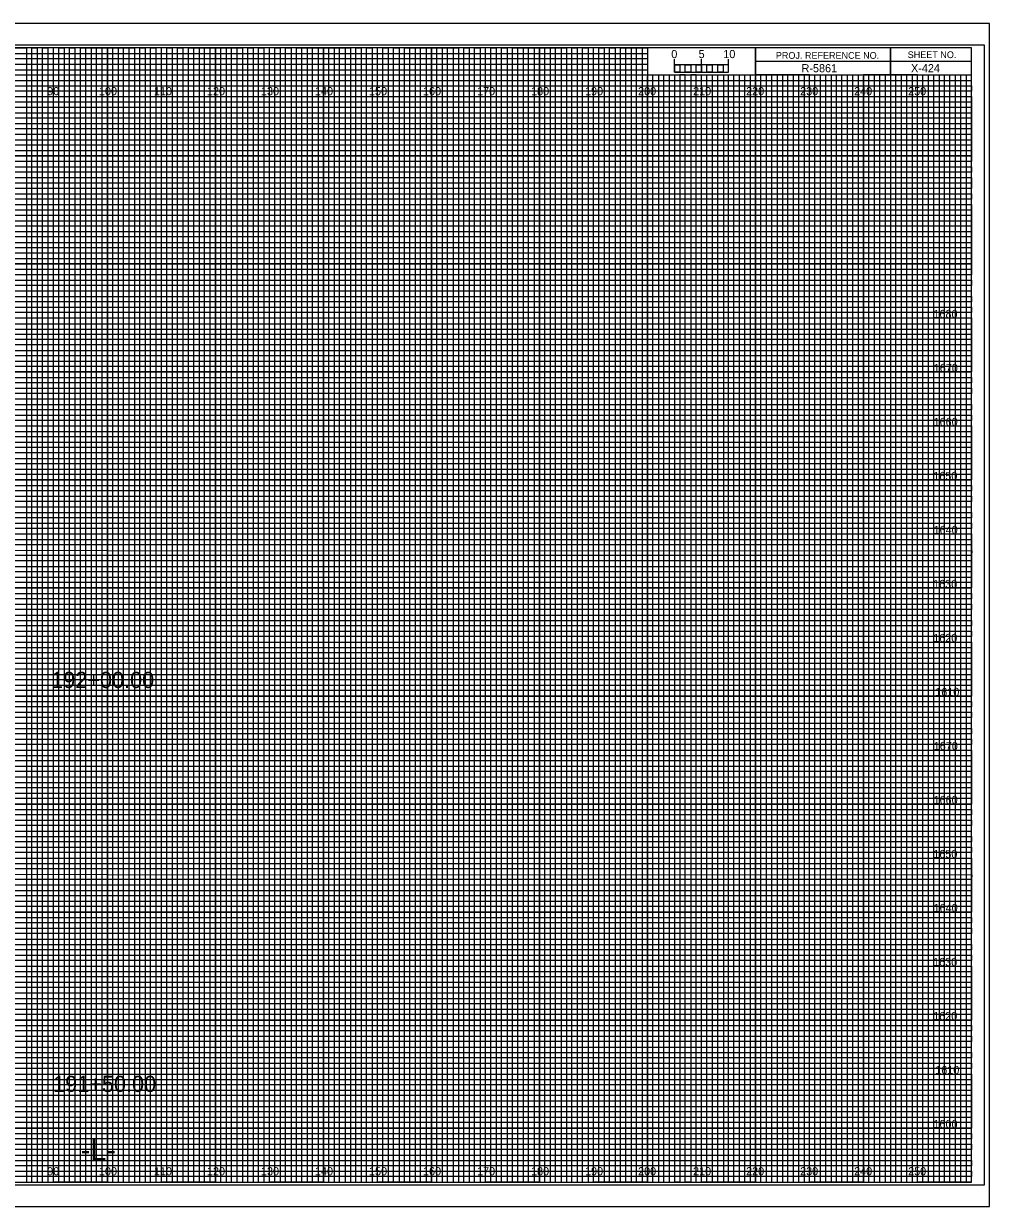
# Model space of a CAD drawing. Extents: x -13 to 323, y -5 to 6154.
# Drawn here: x 144.5 to 323.3, y 4395.5 to 4614.5 of the extents above; entities that cross this region are included whole.
import ezdxf

# ---------------------------------------------------------------- set-up
doc = ezdxf.new("R2010")
doc.units = 0
for name, color, linetype in [('Exist CMT Ground Line', 7, 'Continuous'), ('Prop Horizontal Alignment', 7, 'Continuous'), ('Prop Retaining Wall', 7, 'Continuous'), ('Prop XS Alignment Label', 7, 'Continuous'), ('Prop XS Bar Scale Labels', 7, 'Continuous'), ('Prop XS DDE', 7, 'Continuous'), ('Prop XS DDE Elevations', 7, 'Continuous'), ('Prop XS DDE Slope Text', 7, 'Continuous'), ('Prop XS Earthwork Shape', 7, 'Continuous'), ('Prop XS Elevation Labels', 7, 'Continuous'), ('Prop XS Project Number', 7, 'Continuous'), ('Prop XS Sheet Number', 7, 'Continuous'), ('Prop XS Station Labels', 7, 'Continuous'), ('Raster_Level_0', 7, 'Continuous'), ('Scratch_Level_3', 7, 'Continuous'), ('Sheet Cutting Line CELL', 7, 'Continuous')]:
    doc.layers.add(name, color=color, linetype=linetype)

msp = doc.modelspace()

# ---------------------------------------------------------------- linework, layer by layer
at = {"layer": 'Exist CMT Ground Line'}
for p, q in [((265, 4605.49), (265, 4607.9)), ((265, 4606.9), (265, 4607.9)), ((270, 4605.49), (270, 4607.9)), ((275, 4605.49), (275, 4607.9)), ((275, 4606.9), (275, 4607.9))]:
    msp.add_line(p, q, dxfattribs=at)
for points in [[(275, 4606.9), (265, 4606.9), (265, 4605.49), (275, 4605.49)], [(265, 4606.9), (266, 4606.9), (266, 4605.49), (265, 4605.49)], [(267, 4606.9), (268, 4606.9), (268, 4605.49), (267, 4605.49)], [(269, 4606.9), (270, 4606.9), (270, 4605.49), (269, 4605.49)], [(271, 4606.9), (272, 4606.9), (272, 4605.49), (271, 4605.49)], [(273, 4606.9), (274, 4606.9), (274, 4605.49), (273, 4605.49)]]:
    msp.add_lwpolyline(points, close=True, dxfattribs=at)
at = {"layer": 'Prop Retaining Wall'}
for p, q in [((0, 4609), (260, 4609)), ((260, 4607.98), (0, 4607.98)), ((260, 4609), (260, 4607.98)), ((0, 4607), (260, 4607)), ((260, 4605.89), (0, 4605.89)), ((260, 4607), (260, 4605.89)), ((0, 4604), (320, 4604))]:
    msp.add_line(p, q, dxfattribs=at)
for points in [[(0, 4603), (270, 4603), (320, 4603), (320, 4602), (0, 4602)], [(0, 4601), (320, 4601), (320, 4599), (0, 4599)], [(0, 4598), (320, 4598), (320, 4597), (0, 4596.98)], [(0, 4596), (320, 4596), (320, 4594), (0, 4594)], [(0, 4593), (320, 4593), (320, 4592), (0, 4592)], [(0, 4591), (320, 4591), (320, 4589), (0, 4589)], [(0, 4588), (320, 4588), (320, 4587), (0, 4587)], [(0, 4586), (320, 4586), (320, 4584), (0, 4584)], [(0, 4583), (320, 4583), (320, 4582), (0, 4582)], [(0, 4581), (320, 4581), (320, 4579), (0, 4579)], [(0, 4578), (320, 4578), (320, 4577), (0, 4577)], [(0, 4576), (320, 4576), (320, 4573.95), (320, 4573), (320, 4572), (0, 4572)], [(0, 4574), (320, 4574), (320, 4573), (0, 4573)], [(0, 4571), (320, 4571), (320, 4569), (0, 4569.03)], [(0, 4569.03), (320, 4569), (320, 4568), (0, 4568)], [(0, 4567), (320, 4567), (320, 4566), (0, 4566)], [(0, 4564), (320, 4564), (320, 4563), (0, 4563)], [(0, 4562), (320, 4562), (320, 4561), (0, 4561)], [(-0.07, 4558.89), (320, 4558.89), (320, 4557.88), (-0.07, 4557.88)], [(0, 4557), (320, 4557), (320, 4556), (0, 4556)], [(0, 4554), (320, 4554), (320, 4553), (0, 4553)], [(0, 4552), (320, 4552), (320, 4551), (0, 4551)], [(0, 4549), (320, 4549), (320, 4548), (0, 4548)], [(0, 4547), (320, 4547), (320, 4546), (0, 4546)], [(0, 4544), (320, 4544), (320, 4543), (0, 4543)], [(0, 4542), (320, 4542), (320, 4541), (0, 4541)], [(0, 4539), (320, 4539), (319.99, 4537.98), (0, 4538)], [(0, 4537), (320, 4537), (320, 4536), (0, 4536)], [(0, 4534), (320, 4534), (320, 4533), (0, 4533)], [(0, 4532), (320, 4532), (320, 4531), (0, 4531)], [(0, 4529), (320, 4529), (320, 4528), (0, 4528)], [(0, 4527), (320, 4527), (320, 4526), (0, 4526)], [(0, 4524), (320, 4524), (320, 4523), (0, 4523)], [(0, 4522), (320, 4522), (320, 4521), (0, 4521)], [(0, 4519), (320, 4519), (320, 4518), (0, 4518)], [(0, 4516.99), (320.07, 4516.91), (320, 4516), (0, 4516)], [(0, 4514), (320, 4514), (320, 4513), (0, 4513)], [(0, 4512), (320, 4512), (320, 4511), (0, 4511)], [(0, 4509), (320, 4509), (320, 4508), (0, 4508)], [(0, 4507), (320, 4507), (320, 4506), (0, 4506)], [(0, 4504), (320, 4504), (320, 4503), (0, 4503)], [(0, 4502), (320, 4502), (320, 4501), (0, 4501)], [(0, 4499), (320, 4499), (320, 4498), (0, 4498)], [(0, 4497), (320, 4497), (320, 4496), (0, 4496)], [(0, 4494), (320, 4494), (320, 4493), (0, 4493)], [(0, 4492), (320, 4492), (320, 4491), (0, 4491)], [(0, 4489), (320, 4489), (320, 4488), (0, 4488)], [(0, 4487), (320, 4487), (320, 4486), (0, 4486)], [(0, 4484), (320, 4484), (320, 4483), (0, 4483)], [(0, 4482), (320, 4482), (320, 4481), (0, 4481)], [(0, 4479), (320, 4479), (319.99, 4477.98), (0, 4478)], [(0, 4477), (320, 4477), (320, 4476), (0, 4476)], [(0, 4474), (320, 4474), (320, 4473), (0, 4473)], [(0, 4472), (320, 4472), (320, 4471), (0, 4471)], [(0, 4469), (320, 4469), (320, 4468), (0, 4468)], [(0, 4467), (320, 4467), (320, 4466), (0, 4466)], [(0, 4464), (320, 4464), (320, 4463), (0, 4463)], [(0, 4462), (320, 4462), (320, 4461), (0, 4461)], [(0, 4459), (320, 4459), (320, 4458), (0, 4458)], [(0, 4456.99), (320.07, 4456.91), (320, 4456), (0, 4456)], [(0, 4454), (320, 4454), (320, 4453), (0, 4453)], [(0, 4452), (320, 4452), (320, 4451), (0, 4451)], [(0, 4449), (320, 4449), (320, 4448), (0, 4448)], [(0, 4447), (320, 4447), (320, 4446), (0, 4446)], [(0, 4444), (320, 4444), (320, 4443), (0, 4443)], [(0, 4442), (320, 4442), (320, 4441), (0, 4441)], [(0, 4439), (320, 4439), (320, 4438), (0, 4438)], [(0, 4437), (320, 4437), (320, 4436), (0, 4436)], [(0, 4434), (320, 4434), (320, 4433), (0, 4433)], [(0, 4432), (320, 4432), (320, 4431), (0, 4431)], [(0, 4429), (320, 4429), (320, 4428), (0, 4428)], [(0, 4427), (320, 4427), (320, 4426), (0, 4426)], [(0, 4424), (320, 4424), (320, 4423), (0, 4423)], [(0, 4422), (320, 4422), (320, 4421), (0, 4421)], [(0, 4419), (320, 4419), (320, 4418), (0, 4418)], [(0, 4417), (320, 4417), (320, 4416), (0, 4416)], [(0, 4414), (320, 4414), (320, 4413), (0, 4413)], [(0, 4412), (320, 4412), (320, 4411), (0, 4411)], [(0, 4409), (320, 4409), (320, 4408), (0, 4408)], [(0, 4407), (320, 4407), (320, 4406), (0, 4406)], [(0, 4404), (320, 4404), (320, 4403), (0, 4403)], [(0, 4402), (320, 4402), (320, 4401), (0, 4401)]]:
    msp.add_lwpolyline(points, dxfattribs=at)
at = {"layer": 'Prop XS Alignment Label'}
for p, q in [((305, 4610), (305, 4605)), ((305, 4605), (305, 4610)), ((280, 4607.5), (280, 4605)), ((320, 4607.49), (280, 4607.49)), ((280, 4605), (320, 4605))]:
    msp.add_line(p, q, dxfattribs=at)
for points in [[(320, 4610), (0, 4610), (0, 4400), (320, 4400)], [(280, 4610), (260, 4610), (260, 4605.03), (280, 4605.03)], [(320, 4610), (280, 4610), (280, 4605), (320, 4605)]]:
    msp.add_lwpolyline(points, close=True, dxfattribs=at)
at = {"layer": 'Prop XS DDE'}
msp.add_lwpolyline([(-13.4, 4395.5), (323.3, 4395.5), (323.3, 4614.5), (-13.4, 4614.5)], close=True, dxfattribs=at)
at = {"layer": 'Prop XS DDE Elevations'}
for p, q in [((150, 4400), (150, 4610)), ((160, 4400), (160, 4610)), ((170, 4400), (170, 4610)), ((180, 4400), (180, 4610)), ((190, 4400), (190, 4610)), ((200, 4400), (200, 4610)), ((210, 4400), (210, 4610)), ((220, 4400), (220, 4610)), ((230, 4400), (230, 4610)), ((240, 4400), (240, 4610)), ((250, 4400), (250, 4610)), ((260, 4400), (260, 4604.69)), ((270, 4400), (270, 4604.69)), ((280, 4400), (280, 4604.69)), ((290, 4400), (290, 4604.69)), ((300, 4400), (300, 4604.69)), ((310, 4400), (310, 4604.69)), ((0, 4600), (320, 4600)), ((0, 4590), (320, 4590)), ((0, 4580), (320, 4580)), ((0, 4570), (320, 4570)), ((0, 4560), (320, 4560)), ((0, 4550), (320, 4550)), ((0, 4540), (320, 4540)), ((0, 4530), (320, 4530)), ((0, 4520), (320, 4520)), ((0, 4510), (320, 4510)), ((0, 4500), (320, 4500)), ((0, 4490), (320, 4490)), ((0, 4480), (320, 4480)), ((0, 4470), (320, 4470)), ((0, 4460), (320, 4460)), ((0, 4450), (320, 4450)), ((0, 4440), (320, 4440)), ((0, 4430), (320, 4430)), ((0, 4420), (320, 4420)), ((0, 4410), (320, 4410))]:
    msp.add_line(p, q, dxfattribs=at)
at = {"layer": 'Prop XS DDE Slope Text'}
msp.add_lwpolyline([(-10.8, 4399.5), (322.4, 4399.5), (322.4, 4610.5), (-10.8, 4610.5)], close=True, dxfattribs=at)
at = {"layer": 'Prop XS Earthwork Shape'}
for p, q in [((150, 4610), (140, 4610)), ((150, 4400), (150, 4610)), ((170, 4610), (160, 4610)), ((160, 4610), (160, 4400)), ((170, 4400), (170, 4610)), ((190, 4610), (180, 4610)), ((180, 4610), (180, 4400)), ((190, 4400), (190, 4610)), ((210, 4610), (200, 4610)), ((200, 4610), (200, 4400)), ((210, 4400), (210, 4610)), ((230, 4610), (220, 4610)), ((220, 4610), (220, 4400)), ((230, 4400), (230, 4610)), ((250, 4610), (240, 4610)), ((240, 4610), (240, 4400)), ((250, 4400), (250, 4610)), ((260, 4610), (260, 4400)), ((270, 4400), (270, 4605)), ((290, 4605), (280, 4605)), ((280, 4605), (280, 4400)), ((290, 4400), (290, 4605)), ((310, 4605), (300, 4605)), ((300, 4605), (300, 4400)), ((310, 4400), (310, 4605)), ((160, 4400), (150, 4400)), ((180, 4400), (170, 4400)), ((200, 4400), (190, 4400)), ((220, 4400), (210, 4400)), ((240, 4400), (230, 4400)), ((260, 4400), (250, 4400)), ((280, 4400), (270, 4400)), ((300, 4400), (290, 4400)), ((320, 4400), (310, 4400)), ((320, 4400), (320, 4400))]:
    msp.add_line(p, q, dxfattribs=at)
for points in [[(0, 4600), (320, 4600), (320, 4590), (0, 4590)], [(0, 4580), (320, 4580), (320, 4570), (0, 4570)], [(0, 4560), (320, 4560), (320, 4550), (0, 4550)], [(0, 4540), (320, 4540), (320, 4530), (0, 4530)], [(0, 4520), (320, 4520), (320, 4510), (0, 4510)], [(0, 4500), (320, 4500), (320, 4490), (0, 4490)], [(0, 4480), (320, 4480), (320, 4470), (0, 4470)], [(0, 4460), (320, 4460), (320, 4450), (0, 4450)], [(0, 4440), (320, 4440), (320, 4430), (0, 4430)], [(0, 4420), (320, 4420), (320, 4410), (0, 4410)]]:
    msp.add_lwpolyline(points, dxfattribs=at)
at = {"layer": 'Prop XS Elevation Labels'}
for p, q in [((267, 4605), (266.01, 4605)), ((266.01, 4605), (266.01, 4400)), ((267, 4400), (267, 4605)), ((269, 4605), (268, 4605)), ((268, 4605), (268, 4400)), ((269, 4400), (269, 4605)), ((266.01, 4400), (265, 4400)), ((268, 4400), (267, 4400))]:
    msp.add_line(p, q, dxfattribs=at)
for points in [[(145, 4400), (146, 4400), (146, 4610), (147, 4610), (147, 4400)], [(147, 4400), (148, 4400), (148, 4610), (149, 4610), (149, 4400)], [(150, 4400), (151, 4400), (151, 4610), (152, 4610), (152, 4400)], [(152, 4400), (153, 4400), (153, 4610), (154, 4610), (154, 4400)], [(155, 4400), (156, 4400), (156, 4610), (157, 4610), (157, 4400)], [(157, 4400), (158, 4400), (158, 4610), (159, 4610), (159, 4400)], [(160, 4400), (161, 4400), (161, 4610), (162, 4610), (162, 4400)], [(162, 4400), (163, 4400), (163, 4610), (164, 4610), (164, 4400)], [(165, 4400), (166, 4400), (166, 4610), (167, 4610), (167, 4400)], [(167, 4400), (168, 4400), (168, 4610), (169, 4610), (169, 4400)], [(170, 4400), (171, 4400), (171, 4610), (172, 4610), (172, 4400)], [(172, 4400), (173, 4400), (173, 4610), (174, 4610), (174, 4400)], [(175, 4400), (176, 4400), (176, 4610), (177, 4610), (177, 4400)], [(177, 4400), (178, 4400), (178, 4610), (179, 4610), (179, 4400)], [(180, 4400), (181, 4400), (181, 4610), (182, 4610), (182, 4400)], [(182, 4400), (183, 4400), (183, 4610), (184, 4610), (184, 4400)], [(185, 4400), (186, 4400), (186, 4610), (187, 4610), (187, 4400)], [(187, 4400), (188, 4400), (188, 4610), (189, 4610), (189, 4400)], [(190, 4400), (191, 4400), (191, 4610), (192, 4610), (192, 4400)], [(192, 4400), (193, 4400), (193, 4610), (194, 4610), (194, 4400)], [(195, 4400), (196, 4400), (196, 4610), (197, 4610), (197, 4400)], [(197, 4400), (198, 4400), (198, 4610), (199, 4610), (199, 4400)], [(200, 4400), (201, 4400), (201, 4610), (202, 4610), (202, 4400)], [(202, 4400), (203, 4400), (203, 4610), (204, 4610), (204, 4400)], [(205, 4400), (206, 4400), (206, 4610), (207, 4610), (207, 4400)], [(207, 4400), (208, 4400), (208, 4610), (209, 4610), (209, 4400)], [(210, 4400), (211, 4400), (211, 4610), (212, 4610), (212, 4400)], [(212, 4400), (213, 4400), (213, 4610), (214, 4610), (214, 4400)], [(215, 4400), (216, 4400), (216, 4610), (217, 4610), (217, 4400)], [(217, 4400), (218, 4400), (218, 4610), (219, 4610), (219, 4400)], [(220, 4400), (221, 4400), (221, 4610), (222, 4610), (222, 4400)], [(222, 4400), (223, 4400), (223, 4610), (224, 4610), (224, 4400)], [(225, 4400), (226, 4400), (226, 4610), (227, 4610), (227, 4400)], [(227, 4400), (228, 4400), (228, 4610), (229, 4610), (229, 4400)], [(230, 4400), (231, 4400), (231, 4610), (232, 4610), (232, 4400)], [(232, 4400), (233, 4400), (233, 4610), (234, 4610), (234, 4400)], [(235, 4400), (236, 4400), (236, 4610), (237, 4610), (237, 4400)], [(237, 4400), (238, 4400), (238, 4610), (239, 4610), (239, 4400)], [(240, 4400), (241, 4400), (241, 4610), (242, 4610), (242, 4400)], [(242, 4400), (243, 4400), (243, 4610), (244, 4610), (244, 4400)], [(245, 4400), (246, 4400), (246, 4610), (247, 4610), (247, 4400)], [(247, 4400), (248, 4400), (248, 4610), (249, 4610), (249, 4400)], [(250, 4400), (251, 4400), (251, 4610), (252, 4610), (252, 4400)], [(252, 4400), (253, 4400), (253, 4610), (254, 4610), (254, 4400)], [(255, 4400), (256, 4400), (256, 4610), (257, 4610), (257, 4400)], [(257, 4400), (258, 4400), (258, 4610), (259, 4610), (259, 4400)], [(260, 4400), (261, 4400), (261, 4605), (262.02, 4605), (262.02, 4400)], [(262, 4400), (263, 4400), (263, 4605), (263.99, 4605), (263.99, 4400)], [(270, 4400), (270.98, 4400), (270.98, 4605), (272, 4605), (272, 4400)], [(272, 4400), (273, 4400), (273, 4605), (274.05, 4605), (274.05, 4400)], [(275, 4400), (276, 4400), (276, 4605), (277, 4605), (277, 4400)], [(277, 4400), (278, 4400), (278, 4605), (279, 4605), (279, 4400)], [(280, 4400), (281, 4400), (281, 4605), (282, 4605), (282, 4400)], [(282, 4400), (283, 4400), (283, 4605), (284, 4605), (284, 4400)], [(285, 4400), (286, 4400), (286, 4605), (287, 4605), (287, 4400)], [(287, 4400), (288, 4400), (288, 4605), (289, 4605), (289, 4400)], [(290, 4400), (291, 4400), (291, 4605), (292, 4605), (292, 4400)], [(292, 4400), (293, 4400), (293, 4605), (294, 4605), (294, 4400)], [(295, 4400), (296, 4400), (296, 4605), (297, 4605), (297, 4400)], [(297, 4400), (298, 4400), (298, 4605), (299, 4605), (299, 4400)], [(300, 4400), (301, 4400), (301, 4605), (302, 4605), (302, 4400)], [(302, 4400), (303, 4400), (303, 4605), (304, 4605), (304, 4400)], [(305, 4400), (306, 4400), (306, 4605), (307, 4605), (307, 4400)], [(307, 4400), (308, 4400), (308, 4605), (309, 4605), (309, 4400)], [(310, 4400), (311, 4400), (311, 4605), (312, 4605), (312, 4400)], [(312, 4400), (313, 4400), (313, 4605), (314, 4605), (314, 4400)], [(315, 4400), (316, 4400), (316, 4605), (317, 4605), (317, 4400)], [(317, 4400), (318, 4400), (318, 4605), (319, 4605), (319, 4400)]]:
    msp.add_lwpolyline(points, dxfattribs=at)
at = {"layer": 'Prop XS Station Labels'}
for points in [[(135, 4610), (145, 4610), (145, 4400), (155, 4400), (155, 4610), (165, 4610), (165, 4400), (175, 4400), (175, 4610), (185, 4610), (185, 4400), (195, 4400), (195, 4610), (205, 4610), (205, 4400), (215, 4400), (215, 4610), (225, 4610), (225, 4400), (235, 4400), (235, 4610), (245, 4610), (245, 4400), (255, 4400), (255, 4610), (259.93, 4610), (260, 4610), (260, 4605), (264.99, 4605), (264.99, 4400), (275, 4400), (275, 4605), (285, 4605), (285, 4400), (295, 4400), (295, 4605), (305, 4605), (305, 4400), (315, 4400), (315, 4605)], [(0, 4605), (275, 4605)], [(0, 4585), (320, 4585), (320, 4595), (0, 4595)], [(0, 4565), (320, 4565), (320, 4575), (0, 4575)], [(0, 4545), (320, 4545), (320, 4555), (0, 4555)], [(0, 4525), (320, 4525), (320, 4535), (0, 4535)], [(0, 4505), (320, 4505), (320, 4515), (0, 4515)], [(0, 4485), (320, 4485), (320, 4495), (0, 4495)], [(0, 4465), (320, 4465), (320, 4475), (0, 4475)], [(0, 4445), (320, 4445), (320, 4455), (0, 4455)], [(0, 4425), (320, 4425), (320, 4435), (0, 4435)], [(0, 4405), (320, 4405), (320, 4415), (0, 4415)]]:
    msp.add_lwpolyline(points, dxfattribs=at)
at = {"layer": 'Sheet Cutting Line CELL'}
for p, q in [((323.3, 4614.5), (-13.4, 4614.5)), ((-13.4, 4395.5), (323.3, 4395.5))]:
    msp.add_line(p, q, dxfattribs=at)

# ---------------------------------------------------------------- texts
at = {"layer": 'Exist CMT Ground Line'}
msp.add_text('0', height=1.5, dxfattribs=at).set_placement((264.41, 4608.12))
at = {"layer": 'Prop Horizontal Alignment'}
for s, p in [('192+00.00', (149.59, 4491.48)), ('191+50.00', (149.95, 4416.68))]:
    msp.add_text(s, height=3, dxfattribs=at).set_placement(p)
at = {"layer": 'Prop XS Alignment Label'}
for s, height, p in [('PROJ. REFERENCE NO.', 1.25, (283.77, 4607.99)), ('SHEET NO.', 1.25, (308.19, 4608.12)), ('-L-', 4, (155.06, 4404))]:
    msp.add_text(s, height=height, dxfattribs=at).set_placement(p)
at = {"layer": 'Prop XS Bar Scale Labels'}
for s, p in [('5', (269.47, 4608.12)), ('10', (274.04, 4608.12))]:
    msp.add_text(s, height=1.5, dxfattribs=at).set_placement(p)
at = {"layer": 'Prop XS Project Number'}
msp.add_text('R-5861', height=1.5, dxfattribs=at).set_placement((288.53, 4605.5))
at = {"layer": 'Prop XS Sheet Number'}
msp.add_text('X-424', height=1.5, dxfattribs=at).set_placement((308.8, 4605.51))
at = {"layer": 'Raster_Level_0'}
for s, p in [('90', (148.86, 4601.25)), ('100', (158.44, 4601.25)), ('110', (168.62, 4601.25)), ('120', (178.44, 4601.25)), ('130', (188.44, 4601.25)), ('140', (198.44, 4601.25)), ('150', (208.44, 4601.25)), ('160', (218.44, 4601.25)), ('170', (228.44, 4601.25)), ('180', (238.44, 4601.25)), ('190', (248.44, 4601.25)), ('200', (258.26, 4601.25)), ('210', (268.44, 4601.25)), ('220', (278.26, 4601.25)), ('230', (288.26, 4601.25)), ('240', (298.26, 4601.25)), ('250', (308.26, 4601.25)), ('90', (148.86, 4401.25)), ('100', (158.44, 4401.25)), ('110', (168.62, 4401.25)), ('120', (178.44, 4401.25)), ('130', (188.44, 4401.25)), ('140', (198.44, 4401.25)), ('150', (208.44, 4401.25)), ('160', (218.44, 4401.25)), ('170', (228.44, 4401.25)), ('180', (238.44, 4401.25)), ('190', (248.44, 4401.25)), ('200', (258.26, 4401.25)), ('210', (268.44, 4401.25)), ('220', (278.26, 4401.25)), ('230', (288.26, 4401.25)), ('240', (298.26, 4401.25)), ('250', (308.26, 4401.25))]:
    msp.add_text(s, height=1.5, dxfattribs=at).set_placement(p)
at = {"layer": 'Scratch_Level_3'}
for s, p in [('1680', (312.95, 4560)), ('1670', (313, 4550)), ('1660', (312.97, 4540)), ('1650', (312.92, 4530)), ('1640', (312.97, 4520)), ('1630', (312.89, 4510)), ('1620', (312.9, 4500)), ('1610', (313.28, 4490)), ('1670', (313, 4480)), ('1660', (312.97, 4470)), ('1650', (312.92, 4460)), ('1640', (312.97, 4450)), ('1630', (312.89, 4440)), ('1620', (312.9, 4430)), ('1610', (313.28, 4420)), ('1600', (312.95, 4410))]:
    msp.add_text(s, height=1.5, dxfattribs=at).set_placement(p)

doc.saveas('drawing.dxf')
